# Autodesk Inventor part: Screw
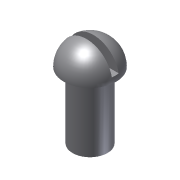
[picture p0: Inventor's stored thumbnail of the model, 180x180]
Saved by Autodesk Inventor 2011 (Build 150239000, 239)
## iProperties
Created: 2009-04
Part Number: Screw
Document SubType Name: Modeling
Designer: Sham
Density: 1 g/cm^3
Author: Sham
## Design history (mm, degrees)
sketch "Sketch1"
  geometry: C1 r 10 at (0, 0)
  constraints: 1 centre point
  dimensions: "d0" = 20 diameter of C1
extrude "Extrusion1" new body sketch "Sketch1" distance "d1" = 38; taper "d2" = 0 deg
sketch "Sketch2"
  geometry: L1 (0, 38)-(-15, 38); L2 (-10, 38)-(10, 38) reference; L3 (0, 38)-(0, 53); A1 r 15 centre (0, 38) between (0, 53) and (-15, 38)
  constraints: 4 end point, 2 point on circle, 1 centre point, 1 collinear, 1 perpendicular
  dimensions: "d3" = 15 radius of A1
revolve "Revolution1" sketch "Sketch2" stored, may be unused: angle "d4" = 90 deg
sketch "Sketch3"
  geometry: L1 (2, 54)-(2, 41); L2 (2, 41)-(-2, 41); L3 (-2, 41)-(-2, 54); L4 (-2, 54)-(2, 54); L5 (15, 38)-(-15, 38) reference
  constraints: 8 end point, 2 parallel, 1 perpendicular, 1 vertical
  dimensions: "d5" = 3 distance between parallel lines of L5 L2; "d6" = 4 distance between parallel lines of L3 L1
extrude "Extrusion2" cut sketch "Sketch3" stored distance "d7" = 38; taper "d8" = 0 deg
body "Solid1"
